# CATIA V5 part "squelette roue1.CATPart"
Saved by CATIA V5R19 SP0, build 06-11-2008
Part number: squelette roue1
Publications: "Plan.1", "Point.1", "Point.2", "Point.4", "Point.8", "Point.9", "Point.10", "Longueur du tube", "rayon2 de l'antiboue", "rayon1 de l'antiboue", "rayon de l'axe", "epaisseur du roue", "Longueur du roue", "Plan.3", "Droite.3", "angle de l'antiboue", "Point.11", "Plan.4", "Point.14", "Point.13", "Droite.8", "Droite.7", "Point.12", "Droite.6", "Plan.5", "position vertical du pivot", "position horizontal du pivot", "rayon1 du tube", "rayon2 du tube", "epaisseur du pivot", "demi-distance entre les des pivot", "rayon du trou des liaisons"
Bounding box of the stored display mesh (mm): x 0 to 45, y -40 to 40, z 0 to 450
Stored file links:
  I:\yyang\yyang\squelette roue1.CATPart
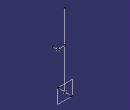
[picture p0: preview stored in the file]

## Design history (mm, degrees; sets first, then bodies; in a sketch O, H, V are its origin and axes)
Parameters
  `Longueur du tube` = 450 mm
  `angle de l'antiboue` = 40 deg
  `epaisseur du roue` = 32 mm
  `Longueur du roue` = 54 mm
  `rayon2 de l'antiboue` = 25 mm
  `rayon1 de l'antiboue` = 30 mm
  `rayon de l'axe` = 5 mm
  `position vertical du pivot1` = 250 mm
  `position horizontal du pivot1` = 45 mm
  `rayon1 du tube` = 21 mm
  `rayon2 du tube` = 18 mm
  `demi-distance entre les des pivot` = 9 mm
  `epaisseur du pivot` = 2 mm
  `rayon du trou des liaisons` = 5 mm
Body1 (main body)
  Plane1: type Offset, Offset 0, RefPlane yz-plane
  Point1: (0, 0, 54 {= `Longueur du roue`})
  Point2: (0, 16 {= `epaisseur du roue` /2}, 0)
  Point3: (0, 0, -54 {= -`Longueur du roue`})
  Point4: (0, 0, 0)
  Point5: (0, 0, 79 {= `Longueur du roue` +`rayon2 de l'antiboue`})
  Point6: (0, 0, 84 {= `Longueur du roue`+`rayon1 de l'antiboue`})
  Plane2: type Offset, Offset 0, RefPlane zx-plane
  Line1: type PtDir, Direction (0, 1, 0), Start -40, End 40, RefPoint Point4
  Point7: (0, 0, 5 {= `rayon de l'axe`})
  Plane3: type Offset, Offset 0, RefPlane xy-plane
  Plane4: type Offset, Offset 450 {= `Longueur du tube`}, RefPlane Plane3
  Line2: type PtDir, LineFirstUpto Plane4, Direction (0, 0, 1), Start 0, End 0, RefPoint Point4
  Point8: (45 {= `position horizontal du pivot1`}, 0, 250 {= `position vertical du pivot1`})
  Line3: type PtDir, LineFirstUpto Line2, Direction (1, 0, 0), Start 0, End 0, RefPoint Point8
  Line4: type PtDir, Direction (0, 1, 0), Start 30, End 0, RefPoint Point8
  Point9: (21 {= `rayon1 du tube`}, 0, 450 {= `Longueur du tube`})
  Point10: (18 {= `rayon2 du tube`}, 0, 450 {= `Longueur du tube`})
